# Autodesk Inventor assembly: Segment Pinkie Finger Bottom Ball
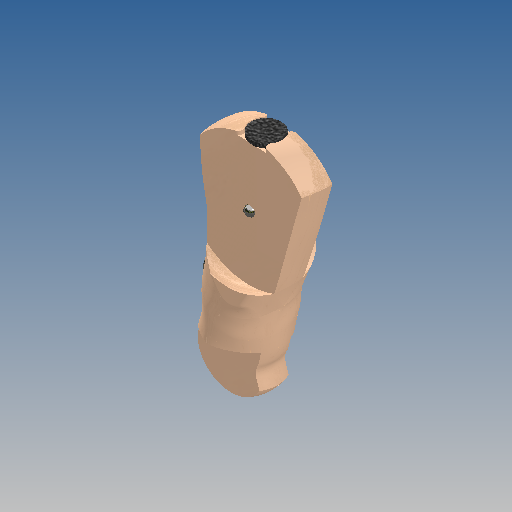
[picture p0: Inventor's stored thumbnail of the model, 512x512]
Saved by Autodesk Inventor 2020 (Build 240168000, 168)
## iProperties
Created: 2019-10
Part Number: Segment Pinkie Finger Bottom Ball
Document SubType Name: Assembly
Designer: yello
Author: yello
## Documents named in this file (7)
- C:\Users\yello\Documents\Mechanical Hand\Prototype 2 (Realistic Hand)\Segment Pinkie Finger Bottom Ball.iam
- C:\Users\yello\Documents\Mechanical Hand\Prototype 2 (Realistic Hand)\Segment Pinkie Finger Bottom.ipt
- C:\Users\yello\Documents\Mechanical Hand\Prototype 2 (Realistic Hand)\Lock.ipt
- C:\Users\yello\Documents\Mechanical Hand\Prototype 2 (Realistic Hand)\Ball.ipt
- C:\Users\yello\Documents\Mechanical Hand\Prototype 2 (Realistic Hand)\Plug 3.ipt
- C:\Users\yello\Documents\Mechanical Hand\Prototype 2 (Realistic Hand)\Push Part.ipt
- C:\Users\yello\Documents\Mechanical Hand\Prototype 2 (Realistic Hand)\Spring.ipt
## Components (7 placed, 6 different names)
1. Segment Pinkie Finger Bottom:1 — Mate:5, Mate:6, Mate:9, Mate:10, Mate:11, Mate:12, Mate:13
2. Ball:1 — Mate:6
3. Ball:2 — Mate:5
4. Push Part:1 — Mate:7, Mate:8, Mate:9
5. Lock:1 — Mate:7, Mate:8, Mate:10
6. Spring:1 — Mate:11
7. Plug 3:1 — Mate:12, Mate:13
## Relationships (9: Mate 9)
- Mate:5: Segment Pinkie Finger Bottom:1 ↔ Ball:2
- Mate:6: Segment Pinkie Finger Bottom:1 ↔ Ball:1
- Mate:7: Push Part:1 ↔ Lock:1
- Mate:8: Push Part:1 ↔ Lock:1
- Mate:9: Segment Pinkie Finger Bottom:1 ↔ Push Part:1
- Mate:10: Segment Pinkie Finger Bottom:1 ↔ Lock:1
- Mate:11: Segment Pinkie Finger Bottom:1 ↔ Spring:1
- Mate:12: Segment Pinkie Finger Bottom:1 ↔ Plug 3:1
- Mate:13: Segment Pinkie Finger Bottom:1 ↔ Plug 3:1
